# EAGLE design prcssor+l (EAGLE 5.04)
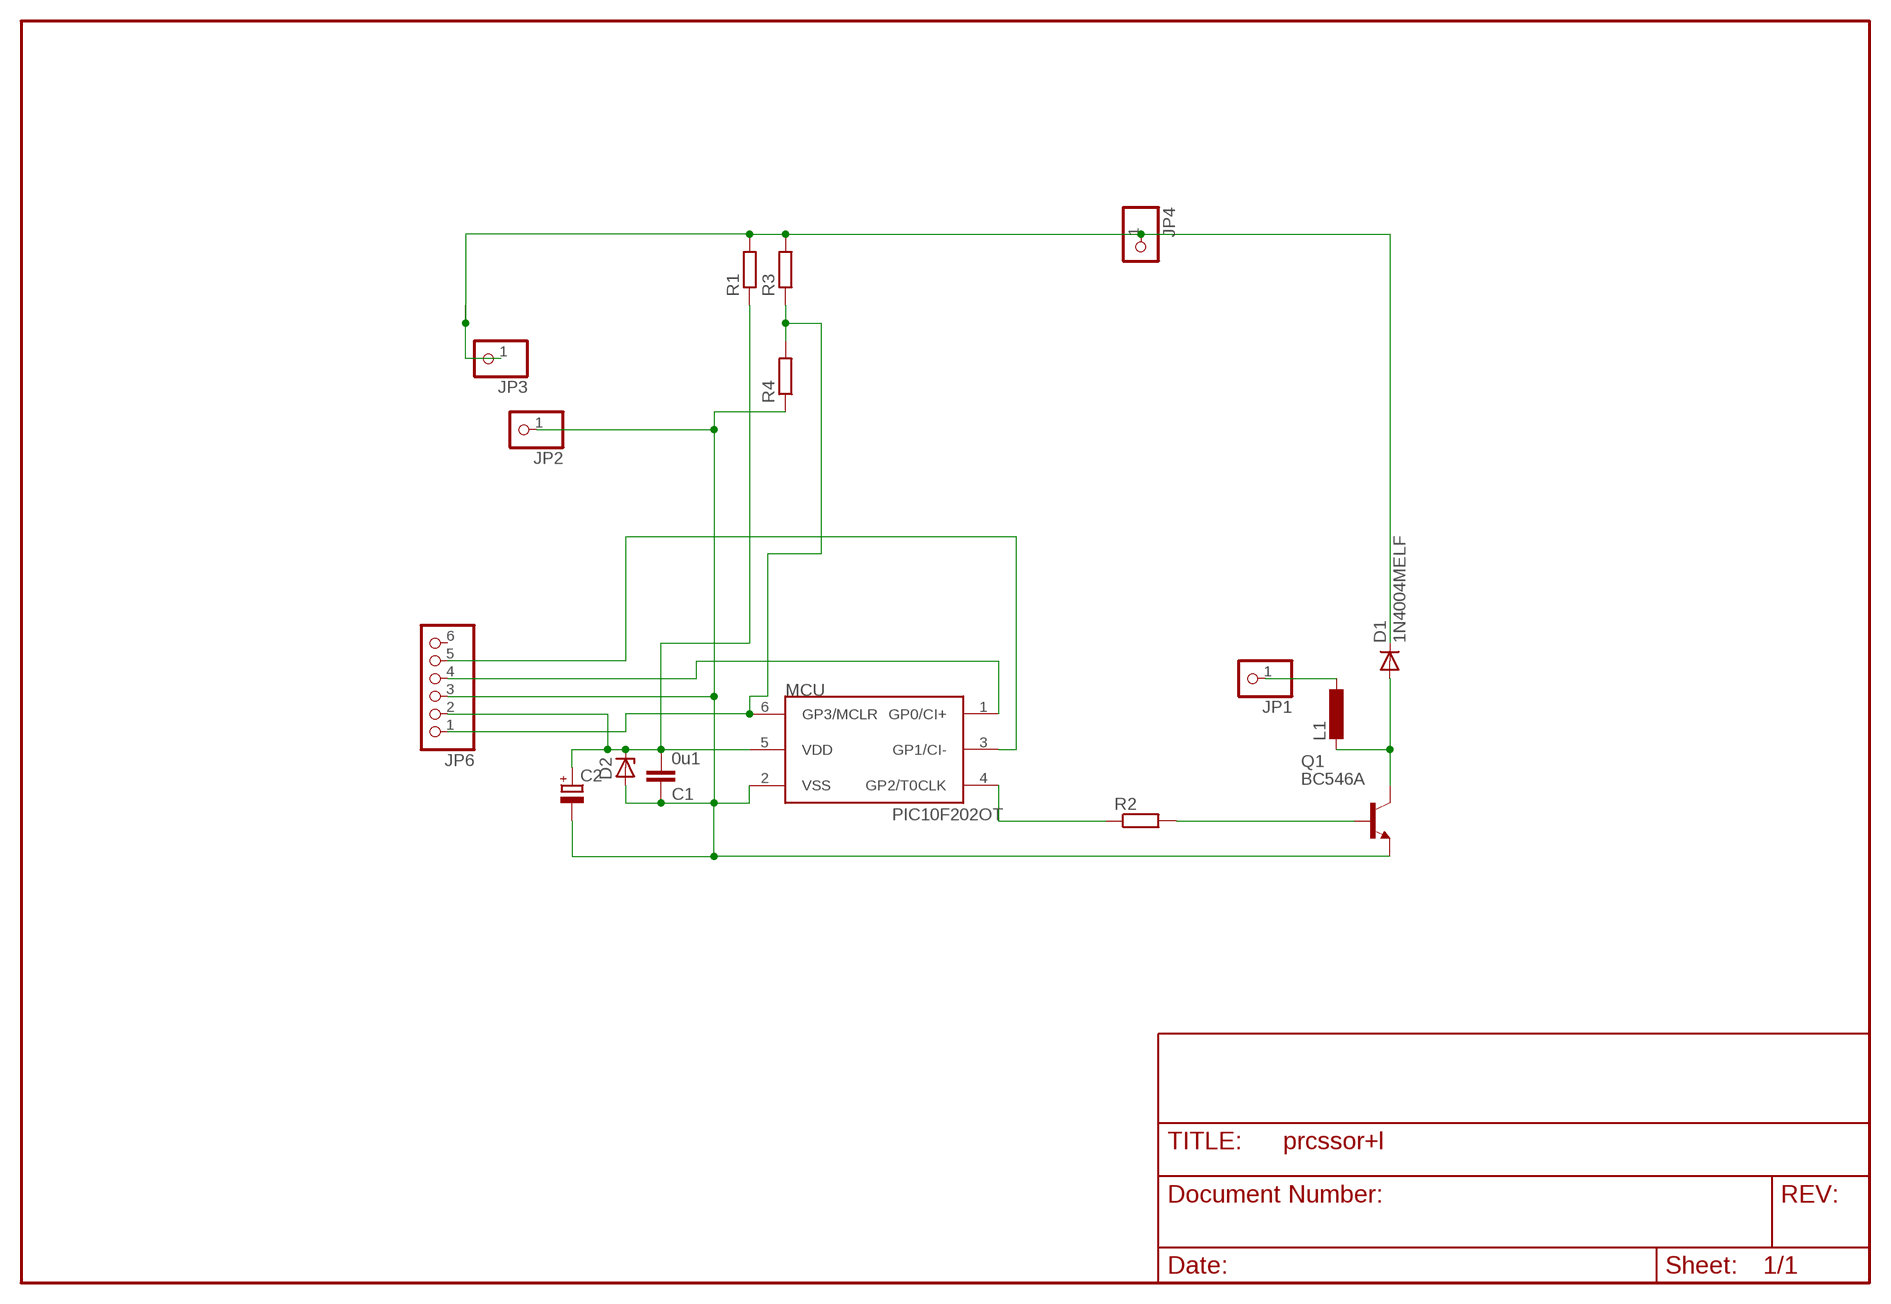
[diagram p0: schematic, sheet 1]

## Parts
C1  0u1  C-EUC0805  [C0805]
C2  CPOL-EUE2.5-5  [E2,5-5]
D1  1N4004MELF  [MELF-MLL41]
D2  ZENER-DIODESOT23  [SOT23]
JP1  PINHD-1X1  [1X01]
JP2  PINHD-1X1  [1X01]
JP3  PINHD-1X1  [1X01]
JP4  PINHD-1X1  [1X01]
JP6  PINHD-1X6  [1X06]
L1  L-EU0207/7  [0207/7]
MCU  PIC10F202OT  [SOT23-6]
Q1  BC546A  [TO92-EBC]
R1  R-EU_M1206  [M1206]
R2  R-EU_R0805  [R0805]
R3  R-EU_R1206  [R1206]
R4  R-EU_R0805  [R0805]

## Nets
GP0: JP6.4 MCU.1(GP0/CI+)
GP1: JP6.5 MCU.3(GP1/CI-)
GP2: MCU.4(GP2/T0CLK) R2.1
GP3: JP6.1 MCU.6(GP3/MCLR) R3.1 R4.2
N$1: Q1.B R2.2
N$2: D1.C JP3.1 JP4.1 R1.2 R3.2
N$3: D1.A L1.2 Q1.C
N$4: JP1.1 L1.1
VDD1: C1.2 C2.+ D2.3(C) JP6.2 MCU.5(VDD) R1.1
VSS1: C1.1 C2.- D2.1(A) JP2.1 JP6.3 MCU.2(VSS) Q1.E R4.1
Unconnected: JP6.6

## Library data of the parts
C1 = rcl:C-EU: CAPACITOR, European symbol
C2 = rcl:CPOL-EU: POLARIZED CAPACITOR, European symbol
D1 = diode-1:1N4004: DIODE
D2 = diode-1:ZENER-DIODE: Z-Diode
JP1-JP4 = pinhead(2):PINHD-1X1: PIN HEADER
JP6 = pinhead(2):PINHD-1X6: PIN HEADER
L1 = rcl:L-EU: INDUCTOR, European symbol
MCU = microchip-3:PIC10F2*: uPC nW 0,25/0,5k Program Flash memory Comparator
Q1 = transistor-npn:BC546*: NPN Transistor
R1-R4 = rcl:R-EU_: RESISTOR, European symbol

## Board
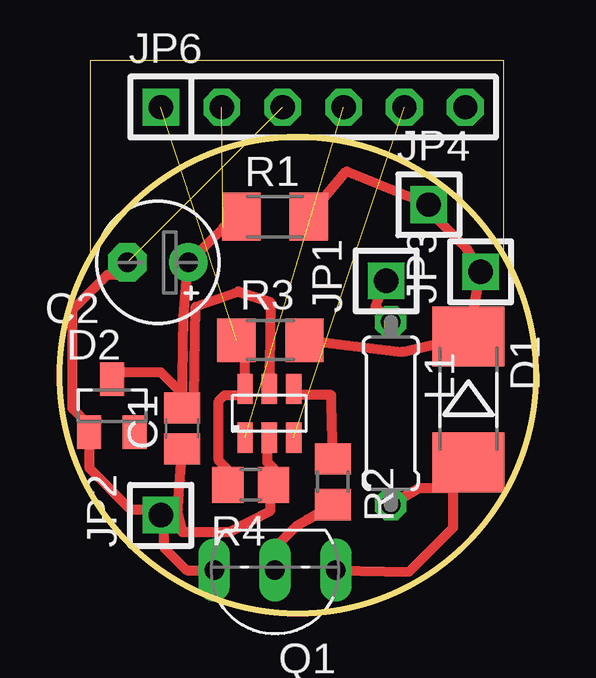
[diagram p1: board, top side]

Size 19.84 x 23.07 mm. Coordinates in mm from the lower left corner, seen from the top.
Outline: 1.28,14.81 1.28,23.06 18.49,23.06 18.49,14.81
Outline: circle at 9.92,9.92 radius 9.92
Copper layers (1*16): Top 0.035mm / dielectric 1.5mm / Bottom 0.035mm
Design rules "default": minimum track width 10mil, minimum drill 24mil, track to track 8mil, track to pad 8mil, pad to pad 8mil, via to via 8mil, smd to smd 8mil, copper to edge 40mil, drill to drill 8mil, minimum pad ring 10mil, minimum via ring 8mil, stop-mask expansion 4mil, vias tented up to drill 0mil, thermal gap 10mil

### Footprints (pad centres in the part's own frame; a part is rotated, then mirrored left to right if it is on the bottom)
C0805 = smd 1.3 x 1.5: 1 -0.85,0; 2 0.85,0
E2,5-5 = drill 0.813 pad 1.6 round: + -1.27,0 | drill 0.813 pad 1.6 octagon: - 1.27,0
MELF-MLL41 = smd 2.5 x 3: A 2.625,0; C -2.625,0
SOT23 = smd 1 x 1.4: 1 -0.95,-1.1; 2 0.95,-1.1; 3 0,1.1
1X01 = drill 1.016 square: 1 0,0
1X06 = drill 1.016 square: 1 -6.35,0 | drill 1.016 octagon: 2 -3.81,0; 3 -1.27,0; 4 1.27,0; 5 3.81,0; 6 6.35,0
0207/7 = drill 0.813 octagon: 1 -3.81,0; 2 3.81,0
SOT23-6 = smd 0.635 x 1.27: 1 -1.016,-1.016; 2 0,-1.016; 3 1.016,-1.016; 4 1.016,1.016; 5 0,1.016; 6 -1.016,1.016
TO92-EBC = drill 0.813 long: B 0,-1.27; C -2.54,-1.27; E 2.54,-1.27
M1206 = smd 1.6 x 2: 1 -1.4,0; 2 1.4,0
R0805 = smd 1.3 x 1.5: 1 -0.95,0; 2 0.95,0
R1206 = smd 1.6 x 1.803: 1 -1.422,0; 2 1.422,0

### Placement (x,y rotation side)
C1  5.09,7.7 90 top
C2  4.08,14.62 180 top
D1  17.03,8.9 270 top
D2  2.17,8.65 0 top
JP1  13.6,13.86 90 top
JP2  4.21,4.08 90 top
JP3  17.54,14.24 90 top
JP4  15.38,17.03 0 top
JP6  10.56,21.1 0 top
L1  13.79,8.33 270 top
MCU  8.73,8.33 0 top
Q1  8.97,0.52 180 top
R1  8.97,16.52 0 top
R2  11.38,5.48 270 top
R3  8.78,11.38 0 top
R4  7.95,5.35 180 top

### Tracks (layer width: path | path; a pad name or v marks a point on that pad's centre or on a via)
GP0  (1 unrouted)
GP1  (1 unrouted)
GP2
  Top 0.406: R2.1 11.32,8.71 11.32,9.1 10,9.1 MCU.4
GP3  (1 unrouted)
  Top 0.406: R4.2 7,5.98 6.62,6.36 6.62,8.84 6.87,9.1 7.46,9.1 MCU.6 7.71,10.7 R3.1
N$1
  Top 0.406: Q1.B 9.22,3 9.86,3.63 10.3,3.89 R2.2
N$2
  Top 0.406: R3.2 14.26,10.89 D1.C 16.97,11.02 JP3.1 16.97,15.19 15.45,16.72 JP4.1 11.95,18.43 R1.2
N$3
  Top 0.406: Q1.C 14.56,1.73 16.4,3.57 16.4,5.2 | 16.4,5.2 D1.A | 16.4,5.2 14.96,5.2 L1.2
N$4
  Top 0.406: JP1.1 13.16,12.78 L1.1
VDD1  (1 unrouted)
  Top 0.406: C1.2 5.09,9.16 4.21,10.05 2.47,10.05 D2.3 | C1.2 5.16,12.36 C2.+ 7,16.24 8.14,16.72 6.81,16.08 R1.1 | MCU.5 8.73,10.29 8.78,12.97 7.44,13.41 5.67,12.78 5.6,9.06 C1.2
VSS1  (1 unrouted)
  Top 0.406: Q1.E 5.29,1.79 4.33,2.75 4.33,3.95 JP2.1 | MCU.2 8.65,7.24 8.65,6.3 8.9,6.05 R4.1 8.78,5.22 8.78,4.27 7.06,3.38 5.09,3.38 4.9,4.14 | JP2.1 4.9,4.14 | 4.9,4.14 C1.1 5.09,7.3 | JP2.1 3.95,4.33 2.94,4.33 1.22,6.04 D2.1 1.22,7.82 0.52,8.52 0.52,12.65 1.98,14.11 2.9,14.11 C2.-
